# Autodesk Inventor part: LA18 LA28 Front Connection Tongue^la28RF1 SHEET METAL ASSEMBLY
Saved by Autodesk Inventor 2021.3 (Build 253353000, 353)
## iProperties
Created: 2023-01
Part Number: LA18 LA28 Front Connection Tongue^la28RF1 SHEET METAL ASSEMBLY
Material: Generic
Document SubType Name: Modeling
Designer: AdminForWorker
Density: 1 g/cm^3
Appearance: Default
Title: LA18 LA28 Front Connection Tongue^la28RF1 SHEET METAL ASSEMBLY
Author: AdminForWorker
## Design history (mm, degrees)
feature "Boss-Extrude1"
body "Solid1"
